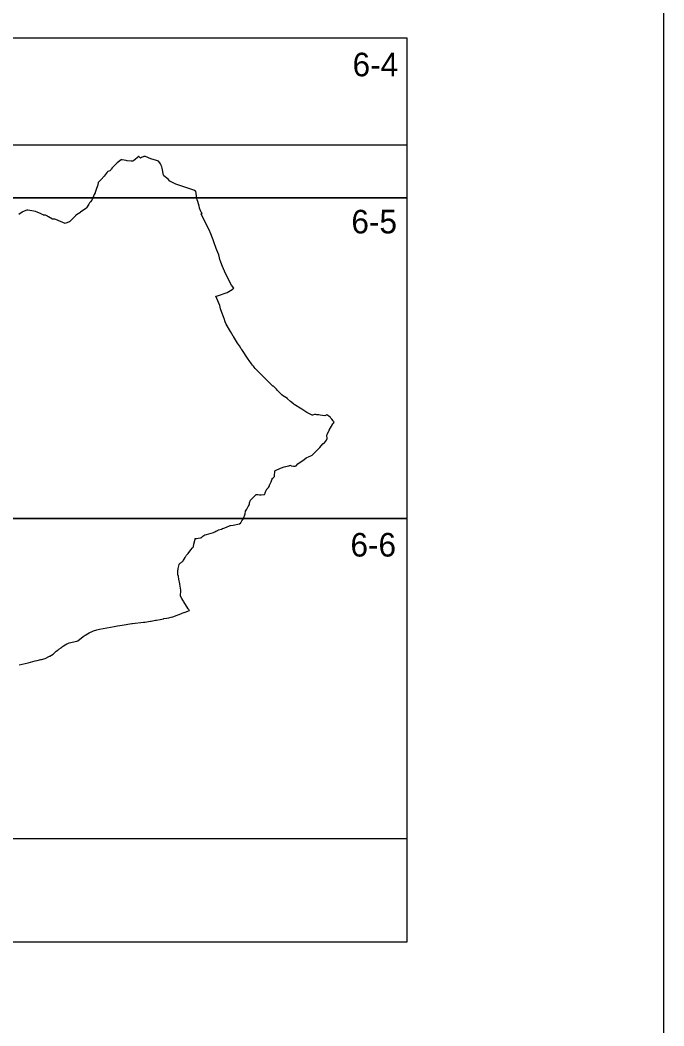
# Model space of a CAD drawing. Extents: x -449577 to -436680, y -1132317 to -1125726.
# Drawn here: x -436931 to -436679.6, y -1130203.9 to -1129811.5 of the extents above; entities that cross this region are included whole.
import ezdxf

# ---------------------------------------------------------------- set-up
doc = ezdxf.new("R2010")
doc.units = 0
for name, color, linetype in [('Vrstva 1', 7, 'Continuous'), ('Vrstva 10', 7, 'Continuous'), ('Vrstva 4', 7, 'Continuous')]:
    doc.layers.add(name, color=color, linetype=linetype)

msp = doc.modelspace()

# ---------------------------------------------------------------- linework, layer by layer
at = {"layer": 'Vrstva 1'}
msp.add_lwpolyline([(-438164.63, -1129516.93), (-438164.63, -1130566.93), (-436679.63, -1130566.93), (-436679.63, -1129516.93)], close=True, dxfattribs=at)
msp.add_lwpolyline([(-436931.34, -1130063.05), (-436927.8, -1130062.18), (-436925.03, -1130061.51), (-436924.36, -1130061.3), (-436922.87, -1130060.94), (-436922.66, -1130060.88), (-436921.23, -1130060.49), (-436920.63, -1130060.23), (-436920.41, -1130060.13), (-436920.25, -1130060.07), (-436919.43, -1130059.62), (-436919.37, -1130059.58), (-436918.06, -1130058.8), (-436916.91, -1130057.75), (-436916.26, -1130057.25), (-436916.13, -1130057.14), (-436916.11, -1130057.13), (-436915.95, -1130057), (-436915.8, -1130056.9), (-436915, -1130056.34), (-436914.94, -1130056.3), (-436914.87, -1130056.25), (-436914.36, -1130055.9), (-436913.99, -1130055.64), (-436913.33, -1130055.18), (-436912.74, -1130054.77), (-436912.58, -1130054.8), (-436912.57, -1130054.8), (-436912.55, -1130054.78), (-436911.82, -1130054.39), (-436908.86, -1130053.81), (-436908.44, -1130053.66), (-436906.41, -1130052.03), (-436905.94, -1130051.69), (-436905.91, -1130051.67), (-436905.55, -1130051.41), (-436905.37, -1130051.29), (-436903.98, -1130050.59), (-436902.57, -1130049.95), (-436902.27, -1130049.8), (-436901.01, -1130049.34), (-436900.01, -1130049.09), (-436894.3, -1130048.03), (-436892.88, -1130047.77), (-436891.17, -1130047.52), (-436887.3, -1130046.95), (-436887.06, -1130046.92), (-436882.76, -1130046.4), (-436882.23, -1130046.34), (-436880.08, -1130045.98), (-436879.76, -1130045.93), (-436878.1, -1130045.66), (-436877.7, -1130045.59), (-436876.29, -1130045.3), (-436875, -1130045.03), (-436874.79, -1130044.99), (-436873.62, -1130044.76), (-436872.95, -1130044.63), (-436872.93, -1130044.63), (-436872.02, -1130044.42), (-436871.95, -1130044.4), (-436871.3, -1130044.24), (-436870.95, -1130044.13), (-436870.06, -1130043.84), (-436869.62, -1130043.69), (-436868.97, -1130043.45), (-436868.85, -1130043.41), (-436867.76, -1130042.92), (-436867.76, -1130042.92), (-436867.64, -1130042.88), (-436866.99, -1130042.65), (-436866.9, -1130042.62), (-436866.47, -1130042.46), (-436864.81, -1130041.88), (-436864.83, -1130041.83), (-436864.94, -1130041.66), (-436865.1, -1130041.43), (-436865.32, -1130041.11), (-436867.02, -1130038.47), (-436867.23, -1130038.12), (-436867.4, -1130037.85), (-436867.84, -1130037.14), (-436868.37, -1130036.29), (-436868.21, -1130033.93), (-436868.2, -1130033.84), (-436868.59, -1130031.54), (-436868.59, -1130031.52), (-436868.6, -1130031.5), (-436868.6, -1130031.5), (-436868.6, -1130031.47), (-436869.01, -1130029.64), (-436869.02, -1130029.45), (-436869.08, -1130028.65), (-436869.18, -1130028.37), (-436869.19, -1130028.35), (-436869.3, -1130028.13), (-436869.34, -1130028.05), (-436869.35, -1130027.67), (-436869.38, -1130026.97), (-436869.33, -1130026.48), (-436869.33, -1130026.46), (-436869.24, -1130025.6), (-436869.22, -1130025.49), (-436868.93, -1130023.85), (-436868.85, -1130023.77), (-436868.55, -1130023.43), (-436868.49, -1130023.36), (-436868.23, -1130023.24), (-436868.17, -1130023.18), (-436867.91, -1130022.98), (-436867.68, -1130022.8), (-436867.47, -1130022.64), (-436867.41, -1130022.6), (-436867.33, -1130022.47), (-436867.25, -1130022.35), (-436867.14, -1130022.18), (-436866.92, -1130021.85), (-436866.5, -1130021.2), (-436866.37, -1130020.95), (-436866.36, -1130020.94), (-436866.22, -1130020.65), (-436866.17, -1130020.56), (-436865.99, -1130020.23), (-436865.85, -1130020.08), (-436865.55, -1130019.77), (-436865.38, -1130019.59), (-436865.1, -1130019.24), (-436864.97, -1130019.07), (-436864.28, -1130018.22), (-436863.62, -1130017.41), (-436863.33, -1130017.05), (-436863.09, -1130015.88), (-436863.03, -1130015.65), (-436862.96, -1130015.37), (-436862.64, -1130014.06), (-436862.56, -1130013.78), (-436862.56, -1130013.75), (-436862.54, -1130013.7), (-436862.38, -1130013.69), (-436862.36, -1130013.69), (-436862.12, -1130013.69), (-436861.43, -1130013.67), (-436861.42, -1130013.67), (-436861.39, -1130013.67), (-436860.71, -1130013.49), (-436860.51, -1130013.43), (-436860.09, -1130013.32), (-436860.07, -1130013.31), (-436860.01, -1130013.25), (-436859.71, -1130012.97), (-436859.59, -1130012.89), (-436859.25, -1130012.63), (-436858.83, -1130012.31), (-436858.76, -1130012.29), (-436858.2, -1130012.13), (-436855.5, -1130011.37), (-436854.91, -1130011.1), (-436854.58, -1130010.94), (-436854.53, -1130010.92), (-436854.43, -1130010.87), (-436854.07, -1130010.69), (-436854.02, -1130010.67), (-436853.99, -1130010.65), (-436853.98, -1130010.65), (-436853.95, -1130010.63), (-436853.64, -1130010.48), (-436853.58, -1130010.44), (-436853.47, -1130010.39), (-436852.39, -1130010.06), (-436851.96, -1130009.88), (-436851.44, -1130009.66), (-436850.43, -1130009.25), (-436849.01, -1130008.62), (-436848.87, -1130008.61), (-436847.74, -1130008.56), (-436845.34, -1130008), (-436844.81, -1130007.6), (-436844.74, -1130007.48), (-436844.65, -1130007.3), (-436844.39, -1130006.79), (-436844.04, -1130006.36), (-436844.02, -1130006.33), (-436843.81, -1130006.04), (-436843.7, -1130005.88), (-436843.69, -1130005.87), (-436843.15, -1130004.09), (-436843.14, -1130004.06), (-436842.94, -1130003.11), (-436842.68, -1130002.65), (-436842.49, -1130002.32), (-436841.94, -1130001.2), (-436841.56, -1130000.69), (-436841.53, -1130000.56), (-436841.46, -1130000.26), (-436841.43, -1130000.12), (-436841.37, -1129999.87), (-436841.35, -1129999.77), (-436841.03, -1129998.76), (-436841.02, -1129998.75), (-436840.73, -1129998.47), (-436840.07, -1129997.84), (-436840.02, -1129997.79), (-436839.55, -1129997.31), (-436839.29, -1129997.05), (-436839.19, -1129996.94), (-436838.82, -1129996.62), (-436838.78, -1129996.62), (-436838.77, -1129996.62), (-436838.36, -1129996.61), (-436838.19, -1129996.62), (-436837.56, -1129996.64), (-436836.85, -1129996.64), (-436835.88, -1129996.55), (-436835.85, -1129996.55), (-436835.6, -1129996.52), (-436835.38, -1129996.16), (-436835.33, -1129996.03), (-436835.31, -1129995.98), (-436835.29, -1129995.92), (-436834.93, -1129994.9), (-436834.79, -1129994.73), (-436834.69, -1129994.62), (-436834.65, -1129994.58), (-436834.59, -1129994.5), (-436834.47, -1129994.37), (-436834.2, -1129994.05), (-436834.11, -1129993.95), (-436834.01, -1129993.83), (-436833.67, -1129993.44), (-436833.6, -1129993.05), (-436833.54, -1129992.74), (-436833.47, -1129992.61), (-436832.92, -1129991.69), (-436832.81, -1129991.3), (-436832.62, -1129990.6), (-436832.5, -1129990.31), (-436832.21, -1129990.04), (-436831.66, -1129989.53), (-436831.59, -1129989.47), (-436831.49, -1129987.36), (-436830.47, -1129986.87), (-436830.07, -1129986.66), (-436829.82, -1129986.53), (-436829.53, -1129986.37), (-436829.31, -1129986.29), (-436828.97, -1129986.16), (-436828.92, -1129986.15), (-436827.83, -1129985.74), (-436827.82, -1129985.74), (-436827.33, -1129985.68), (-436827.25, -1129985.66), (-436826.22, -1129985.4), (-436826.07, -1129985.36), (-436825.98, -1129985.33), (-436825.81, -1129985.28), (-436825.28, -1129985.11), (-436825.28, -1129985.11), (-436825.27, -1129985.12), (-436825.27, -1129985.12), (-436825.24, -1129985.18), (-436825.11, -1129985.4), (-436824.23, -1129985.5), (-436824.03, -1129985.52), (-436823.67, -1129985.56), (-436823.58, -1129985.52), (-436823.15, -1129985.34), (-436822.5, -1129984.63), (-436820.86, -1129983.47), (-436820.77, -1129983.4), (-436820.6, -1129983.29), (-436820.09, -1129982.87), (-436819.34, -1129982.27), (-436818.07, -1129981.7), (-436817.45, -1129981.43), (-436816.91, -1129981.19), (-436816.85, -1129981.16), (-436815.2, -1129979.49), (-436814.36, -1129978.6), (-436814, -1129978.22), (-436812.81, -1129976.86), (-436812.21, -1129976.4), (-436812.16, -1129976.36), (-436811.32, -1129975.35), (-436811.12, -1129974.78), (-436811.21, -1129973.45), (-436810.99, -1129972.96), (-436810.35, -1129971.51), (-436808.89, -1129969.03), (-436808.86, -1129968.98), (-436808.86, -1129968.98), (-436808.84, -1129968.95), (-436808.81, -1129968.91), (-436808.66, -1129968.72), (-436808.4, -1129968.38), (-436808.66, -1129968.08), (-436808.8, -1129967.86), (-436809.27, -1129967.12), (-436809.47, -1129966.93), (-436809.62, -1129966.77), (-436809.81, -1129966.57), (-436810.39, -1129966), (-436811.24, -1129965.53), (-436811.69, -1129965.71), (-436812.02, -1129965.83), (-436813.77, -1129965.56), (-436814.38, -1129965.47), (-436814.52, -1129965.46), (-436815.11, -1129965.44), (-436815.49, -1129965.39), (-436815.65, -1129965.36), (-436815.69, -1129965.36), (-436815.72, -1129965.35), (-436815.72, -1129965.35), (-436815.75, -1129965.36), (-436815.85, -1129965.39), (-436815.98, -1129965.42), (-436816.88, -1129965.66), (-436816.95, -1129965.63), (-436819.02, -1129964.59), (-436821.04, -1129963.31), (-436823.95, -1129961.49), (-436824.11, -1129961.35), (-436824.15, -1129961.32), (-436824.24, -1129961.24), (-436825.38, -1129960.31), (-436826.53, -1129959.26), (-436826.64, -1129959.16), (-436827.85, -1129958.4), (-436828.13, -1129958.17), (-436828.76, -1129957.67), (-436829.07, -1129957.43), (-436829.57, -1129956.9), (-436830.29, -1129956.14), (-436830.44, -1129955.98), (-436830.9, -1129955.49), (-436831.87, -1129954.46), (-436832.07, -1129954.35), (-436832.07, -1129954.35), (-436832.25, -1129954.26), (-436832.45, -1129954.16), (-436833.28, -1129953.33), (-436833.91, -1129952.7), (-436835.09, -1129951.53), (-436836.02, -1129950.59), (-436836.18, -1129950.44), (-436836.62, -1129949.99), (-436836.86, -1129949.75), (-436836.95, -1129949.66), (-436836.99, -1129949.62), (-436837.51, -1129949.1), (-436838.15, -1129948.45), (-436838.23, -1129948.37), (-436838.25, -1129948.35), (-436838.4, -1129948.2), (-436839.23, -1129947.36), (-436839.61, -1129946.86), (-436839.89, -1129946.49), (-436840.21, -1129946.06), (-436840.57, -1129945.58), (-436841.52, -1129944.32), (-436841.89, -1129943.78), (-436844.43, -1129940.04), (-436844.6, -1129939.78), (-436845.37, -1129938.59), (-436846.04, -1129937.58), (-436846.88, -1129936.25), (-436847.68, -1129934.98), (-436847.76, -1129934.85), (-436848.85, -1129933), (-436850.53, -1129930.15), (-436850.53, -1129930.14), (-436850.53, -1129930.14), (-436850.54, -1129930.14), (-436850.87, -1129929.16), (-436851.32, -1129927.86), (-436851.38, -1129927.66), (-436852.76, -1129924.15), (-436853.05, -1129922.9), (-436854.53, -1129919.22), (-436853.9, -1129919.02), (-436850.18, -1129917.78), (-436848.21, -1129916.56), (-436848.03, -1129916.45), (-436847.97, -1129916.41), (-436847.77, -1129916.29), (-436847.5, -1129916.12), (-436848.42, -1129914.93), (-436849.83, -1129912.15), (-436850.58, -1129910.68), (-436851.11, -1129909.52), (-436851.13, -1129909.48), (-436851.19, -1129909.35), (-436851.2, -1129909.32), (-436851.22, -1129909.29), (-436851.26, -1129909.2), (-436851.59, -1129908.47), (-436851.91, -1129907.68), (-436852.62, -1129905.91), (-436853.03, -1129904.87), (-436853.18, -1129904.24), (-436853.44, -1129903.11), (-436854.18, -1129901.22), (-436854.38, -1129900.62), (-436855.32, -1129897.99), (-436855.59, -1129897.27), (-436856.78, -1129894.18), (-436856.85, -1129894), (-436856.88, -1129893.92), (-436860.23, -1129887.11), (-436859.92, -1129886.97), (-436859.9, -1129886.96), (-436860, -1129886.79), (-436860.08, -1129886.69), (-436860.25, -1129886.46), (-436860.31, -1129886.38), (-436860.92, -1129884.9), (-436860.97, -1129884.61), (-436861.07, -1129884.15), (-436861.08, -1129884.09), (-436861.59, -1129882.25), (-436861.89, -1129881.62), (-436861.9, -1129881.54), (-436861.94, -1129881.18), (-436862.08, -1129880.09), (-436862.36, -1129878.25), (-436862.42, -1129878.23), (-436862.72, -1129878.13), (-436863.1, -1129877.87), (-436863.11, -1129877.87), (-436867.41, -1129876.46), (-436870.2, -1129875.48), (-436871.51, -1129874.86), (-436872.48, -1129874.3), (-436873.2, -1129873.52), (-436874.88, -1129872.25), (-436874.94, -1129871.95), (-436875.52, -1129869.25), (-436875.67, -1129868.71), (-436875.85, -1129868.2), (-436875.9, -1129868.04), (-436876.15, -1129867.52), (-436876.4, -1129867.21), (-436876.98, -1129866.52), (-436877.73, -1129866.31), (-436879.91, -1129865.65), (-436882, -1129864.69), (-436882.62, -1129864.69), (-436883.57, -1129865.06), (-436883.7, -1129865.15), (-436883.77, -1129865.2), (-436883.91, -1129865.3), (-436883.95, -1129865.33), (-436883.97, -1129865.31), (-436884.18, -1129865.06), (-436884.43, -1129864.78), (-436884.51, -1129864.68), (-436884.6, -1129864.72), (-436885.11, -1129865.11), (-436885.3, -1129865.26), (-436885.97, -1129865.78), (-436886.72, -1129866.34), (-436887.06, -1129866.56), (-436887.65, -1129866.52), (-436889.13, -1129866.37), (-436889.59, -1129866.28), (-436891.18, -1129865.96), (-436891.48, -1129866.07), (-436892.04, -1129866.42), (-436892.59, -1129866.74), (-436893.08, -1129867.2), (-436893.61, -1129867.69), (-436894.01, -1129868.08), (-436894.02, -1129868.09), (-436894.35, -1129868.43), (-436894.48, -1129868.57), (-436894.99, -1129869.12), (-436895.44, -1129869.67), (-436895.6, -1129869.86), (-436895.96, -1129870.29), (-436896.7, -1129870.62), (-436896.72, -1129870.62), (-436896.92, -1129870.87), (-436897.78, -1129871.89), (-436898.16, -1129872.34), (-436899.29, -1129873.7), (-436899.3, -1129873.71), (-436900.54, -1129874.88), (-436900.66, -1129875.72), (-436900.71, -1129876.09), (-436900.75, -1129876.19), (-436901.23, -1129877.54), (-436901.67, -1129878.78), (-436901.7, -1129878.86), (-436902, -1129879.55), (-436902.93, -1129881.73), (-436902.95, -1129881.74), (-436903.52, -1129882.42), (-436903.82, -1129882.77), (-436903.82, -1129882.78), (-436904.16, -1129883.32), (-436905.03, -1129884.71), (-436905.12, -1129884.85), (-436905.29, -1129884.98), (-436905.82, -1129885.37), (-436906.43, -1129885.82), (-436906.43, -1129885.82), (-436907.4, -1129886.45), (-436907.53, -1129886.54), (-436907.71, -1129886.66), (-436909.01, -1129887.52), (-436909.02, -1129887.53), (-436909.28, -1129887.79), (-436909.4, -1129887.91), (-436909.62, -1129888.14), (-436909.9, -1129888.42), (-436910.47, -1129888.99), (-436911.63, -1129890.15), (-436911.83, -1129890.23), (-436913.33, -1129890.8), (-436916.14, -1129889.68), (-436916.14, -1129889.69), (-436916.15, -1129889.71), (-436917.06, -1129889.33), (-436917.37, -1129889.2), (-436917.39, -1129889.2), (-436917.78, -1129889.2), (-436918.26, -1129889.2), (-436919.82, -1129888.21), (-436920.08, -1129888.08), (-436920.37, -1129887.92), (-436920.43, -1129887.89), (-436920.47, -1129887.87), (-436921.01, -1129887.64), (-436921.06, -1129887.64), (-436921.07, -1129887.64), (-436921.22, -1129887.63), (-436921.34, -1129887.62), (-436921.65, -1129887.6), (-436921.67, -1129887.6), (-436921.67, -1129887.6), (-436921.78, -1129887.56), (-436922.02, -1129887.46), (-436922.62, -1129887.21), (-436922.78, -1129887.14), (-436924.3, -1129886.41), (-436924.92, -1129886.23), (-436925.59, -1129886.03), (-436927.91, -1129885.6), (-436927.92, -1129885.6), (-436928.32, -1129885.71), (-436930.06, -1129886.29), (-436930.19, -1129886.4), (-436931.4, -1129887.36)], dxfattribs=at)
at = {"layer": 'Vrstva 10'}
msp.add_lwpolyline([(-436780.04, -1129860.19), (-436780.04, -1130171.17), (-437112.91, -1130171.17), (-437112.91, -1130005.87), (-437092.54, -1130005.87), (-437092.54, -1129880.87), (-437092.54, -1129860.19), (-436780.04, -1129860.19)], dxfattribs=at)
at = {"layer": 'Vrstva 4'}
msp.add_line((-437092.54, -1129818.37), (-436780.04, -1129818.37), dxfattribs=at)
msp.add_lwpolyline([(-436780.04, -1129818.37), (-436780.04, -1129880.87), (-436936.29, -1129880.87), (-436936.29, -1129818.37)], dxfattribs=at)
for points in [[(-436780.04, -1129880.87), (-436780.04, -1130005.87), (-436936.29, -1130005.87), (-436936.29, -1129880.87)], [(-436780.04, -1130005.87), (-436780.04, -1130130.87), (-436936.29, -1130130.87), (-436936.29, -1130005.87)]]:
    msp.add_lwpolyline(points, close=True, dxfattribs=at)

# ---------------------------------------------------------------- texts
at = {"layer": 'Vrstva 1'}
for s, p in [('6-4', (-436801.17, -1129833.42)), ('6-5', (-436801.62, -1129894.71)), ('6-6', (-436801.99, -1130020.78))]:
    msp.add_text(s, height=9.2, dxfattribs=at).set_placement(p)

doc.saveas('drawing.dxf')
